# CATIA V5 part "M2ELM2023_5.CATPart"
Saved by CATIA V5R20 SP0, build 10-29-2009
Part number: Pièce1
Bounding box of the stored display mesh (mm): x 0 to 94.564, y 0 to 61.485, z -100 to 100
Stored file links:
  E:\0 Pedagogie\01 Hamma Lakhdar University\0Pedagogie\2023 2024\M2ELM CFAO\Travail a domicile 3\M2ELM2023_5.CATPart
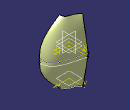
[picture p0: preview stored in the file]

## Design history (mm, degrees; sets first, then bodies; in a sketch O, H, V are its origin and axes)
Set1
  Sketch1 on xy-plane, origin (0, 0, 0), H (1, 0, 0), V (0, 1, 0)
    spline S1 through (0, 61.485) (50.8399, 47.5829) (83.3418, 31.0815) (94.3424, 0.0789)
    point P1 (0, 61.485)
    coincidence: P1 V
  Plane1: type Offset, RefPlane xy-plane, Offset -100
  Sketch2 on Plane1, origin (0, 0, -100), H (1, 0, 0), V (0, 1, 0)
    spline S1 through (0, 44.2779) (20.4642, 30.0611) (34.5205, 23.8847) (40.4838, 9.6151)
    point P1 (0, 44.2779)
    coincidence: P1 V
  Plane2: type Offset, RefPlane xy-plane, Offset -10
  Sketch3 on Plane2, origin (0, 0, -10), H (1, 0, 0), V (0, 1, 0)
    spline S1 through (94.5632, 0.2618) (87.2651, 26.5716) (51.1649, 47.6306) (1.0258, 60.6671)
  Loft1: Sections (Sketch1; Sketch3; Sketch2)
  Symmetry1: ToTransfor Loft1, Reference xy-plane
Body1 (main body)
